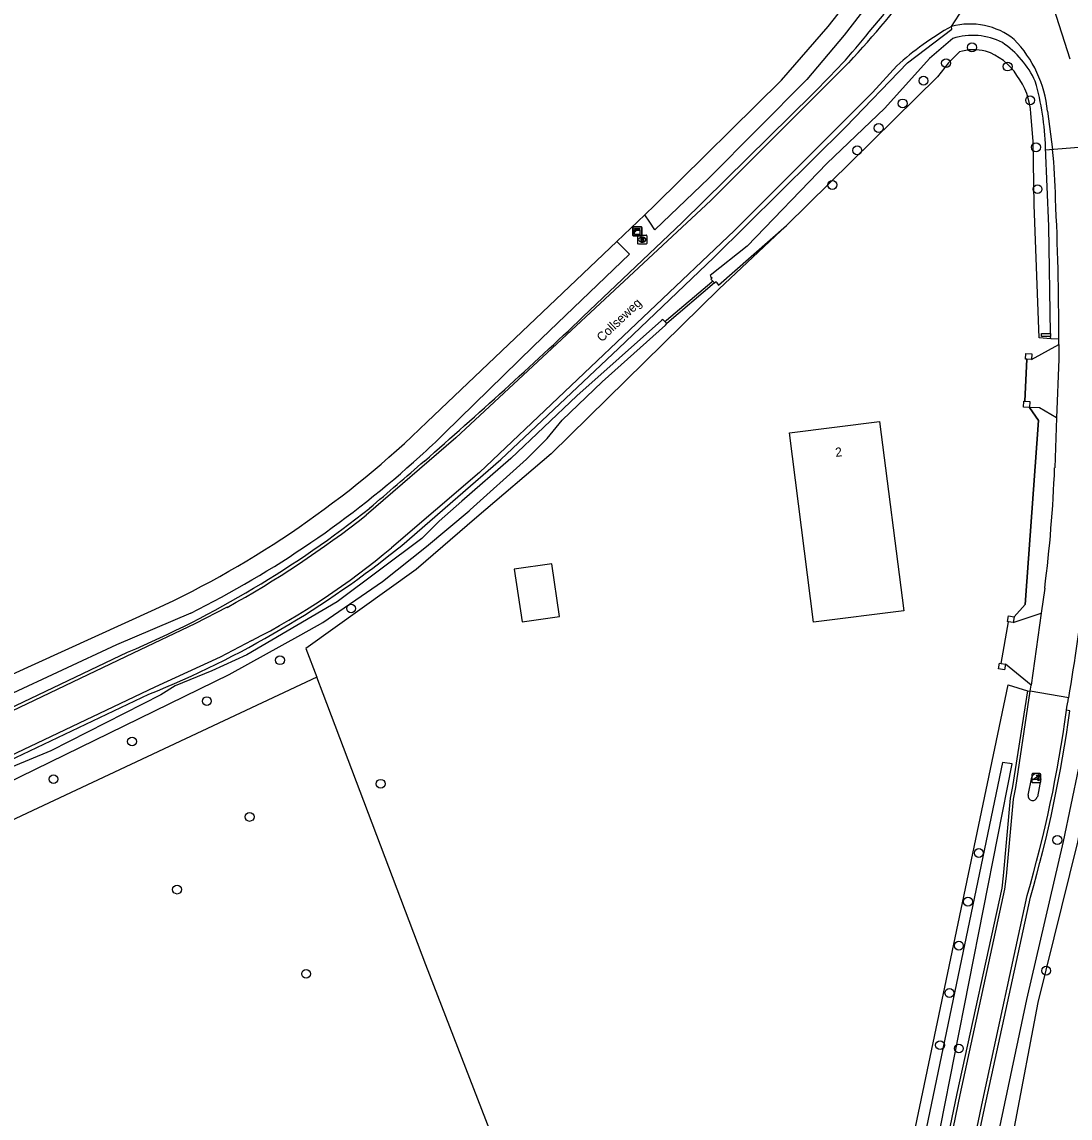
# Model space of a CAD drawing. Extents: x 164494 to 166241, y 382475 to 384494.
# Drawn here: x 165113.4 to 165228.9, y 383751 to 383871.8 of the extents above; entities that cross this region are included whole.
import ezdxf

# ---------------------------------------------------------------- set-up
doc = ezdxf.new("R2010")
doc.units = 0
for name, color, linetype in [('IMGEO_Berm_halfverhard', 7, 'Continuous'), ('IMGEO_Boom', 7, 'Continuous'), ('IMGEO_Bouwland', 7, 'Continuous'), ('IMGEO_Duiker', 7, 'Continuous'), ('IMGEO_Erf', 7, 'Continuous'), ('IMGEO_Groenvoorziening', 7, 'Continuous'), ('IMGEO_Hek', 7, 'Continuous'), ('IMGEO_Kast', 7, 'Continuous'), ('IMGEO_Muur', 7, 'Continuous'), ('IMGEO_Openbare_ruimte_label', 7, 'Continuous'), ('IMGEO_Pand', 7, 'Continuous'), ('IMGEO_Pand_nummerreeks', 7, 'Continuous'), ('IMGEO_Poller', 7, 'Continuous'), ('IMGEO_Rijbaan_lokaal_gesloten', 7, 'Continuous'), ('IMGEO_Rijbaan_lokaal_open', 7, 'Continuous'), ('IMGEO_Rioolput', 7, 'Continuous'), ('IMGEO_Voetpad_open', 7, 'Continuous'), ('IMGEO_Waterloop', 7, 'Continuous')]:
    doc.layers.add(name, color=color, linetype=linetype)

msp = doc.modelspace()

# ---------------------------------------------------------------- linework, layer by layer
at = {"layer": 'IMGEO_Berm_halfverhard'}
for points in [[(165206.74, 383870.72), (165208.37, 383872.67)], [(165155.21, 383814.13), (165161.39, 383819.48), (165166.15, 383823.61), (165179.1, 383835.82), (165189.6, 383845.87), (165204.16, 383860.28), (165210.96, 383867.3), (165215.83, 383871.02), (165215.8, 383871.33)], [(165175.19, 383839.32), (165186.12, 383849.72), (165200.47, 383863.87)], [(165070.12, 383776.3), (165070.84, 383776.64), (165070.9, 383776.54), (165125.01, 383802.35)], [(165072.47, 383771.52), (165073.32, 383771.92), (165073.3, 383772.01), (165127.34, 383797.73)]]:
    msp.add_lwpolyline(points, dxfattribs=at)
for centre, radius, start, end in [((165149.31, 383916.98), 73.74, 313.9288, 321.1451), ((164779.69, 384256.64), 574.96, 311.10726, 313.46198), ((164761.97, 384277.25), 602.13, 310.33243, 311.08901), ((165079.94, 383908.37), 115.2, 293.032, 308.5215), ((165087.22, 383897.79), 107.81, 291.8507, 309.1027)]:
    msp.add_arc(centre, radius, start, end, dxfattribs=at)
at = {"layer": 'IMGEO_Boom'}
for centre in [(165218.05, 383869.02), (165215.2, 383867.28), (165221.98, 383866.91), (165212.71, 383865.35), (165210.42, 383862.84), (165224.46, 383863.19), (165207.77, 383860.13), (165225.11, 383858.01), (165205.41, 383857.67), (165202.67, 383853.86), (165225.28, 383853.39), (165149.64, 383807.17), (165141.8, 383801.47), (165133.74, 383796.96), (165125.5, 383792.51), (165116.84, 383788.36), (165152.89, 383787.85), (165138.45, 383784.2), (165227.46, 383781.65), (165218.81, 383780.22), (165130.46, 383776.19), (165217.61, 383774.86), (165216.61, 383770.01), (165226.23, 383767.25), (165144.68, 383766.9), (165215.57, 383764.79), (165214.54, 383759.04), (165216.61, 383758.67)]:
    msp.add_circle(centre, 0.489, dxfattribs=at)
at = {"layer": 'IMGEO_Bouwland'}
for points in [[(165178.91, 383847.63), (165182.01, 383850.58)], [(165145.85, 383799.61), (165106.62, 383781.19), (165067, 383763.68), (165014.17, 383738.3)], [(165207.26, 383727.36), (165189.95, 383730.66), (165170.64, 383734.86), (165157.89, 383767.91), (165146.55, 383797.78), (165145.85, 383799.61)]]:
    msp.add_lwpolyline(points, dxfattribs=at)
at = {"layer": 'IMGEO_Duiker'}
for points in [[(165226.15, 383857.73), (165232.12, 383858.21)], [(165184.22, 383838.79), (165184.39, 383838.94), (165189.37, 383843.18), (165189.48, 383843.28)]]:
    msp.add_lwpolyline(points, dxfattribs=at)
at = {"layer": 'IMGEO_Erf'}
for points in [[(165224.1, 383834.65), (165223.97, 383834.65), (165224, 383835.29), (165224.64, 383835.26), (165224.61, 383834.62)], [(165224.38, 383829.34), (165223.73, 383829.38), (165223.77, 383830.02), (165223.89, 383830.01)], [(165222.09, 383805.71), (165221.96, 383805.73), (165222.09, 383806.37), (165222.7, 383806.25)], [(165221.74, 383801.03), (165221.63, 383800.4), (165220.99, 383800.51), (165221.1, 383801.14), (165221.26, 383801.11)]]:
    msp.add_lwpolyline(points, dxfattribs=at)
at = {"layer": 'IMGEO_Groenvoorziening'}
for points in [[(165197.6, 383849.39), (165190.2, 383842.41), (165171.67, 383824.21), (165163.5, 383817.22), (165156.8, 383811.47), (165144.65, 383802.77), (165145.85, 383799.61)], [(165189.69, 383843.07), (165184.43, 383838.59)], [(165227.62, 383836.85), (165226.73, 383836.91)], [(165222.7, 383806.25), (165223.9, 383807.6), (165225.39, 383827.88), (165224.38, 383829.34)], [(165222.7, 383806.25), (165222.61, 383805.61)], [(165207.26, 383727.36), (165211.82, 383750), (165222.05, 383798.74), (165224.17, 383798.09)]]:
    msp.add_lwpolyline(points, dxfattribs=at)
at = {"layer": 'IMGEO_Hek'}
for points in [[(165224.1, 383834.65), (165223.89, 383830.01)], [(165224.38, 383829.34), (165225.39, 383827.88), (165223.9, 383807.6), (165222.7, 383806.25)], [(165221.26, 383801.11), (165222.09, 383805.71)]]:
    msp.add_lwpolyline(points, dxfattribs=at)
at = {"layer": 'IMGEO_Kast'}
for p, q in [((165180.67, 383848.32), (165180.67, 383849.16)), ((165180.67, 383849.16), (165180.67, 383848.32)), ((165180.74, 383849.25), (165181.58, 383849.25)), ((165181.58, 383849.25), (165180.74, 383849.25)), ((165181.66, 383849.17), (165181.66, 383848.33)), ((165181.66, 383848.33), (165181.66, 383849.17)), ((165181.59, 383848.25), (165180.75, 383848.25)), ((165180.75, 383848.25), (165181.59, 383848.25))]:
    msp.add_line(p, q, dxfattribs=at)
for points in [[(165180.86, 383849.04), (165181.46, 383849.04), (165181.46, 383848.95), (165180.86, 383848.95), (165180.86, 383849.04)], [(165180.86, 383848.86), (165181.46, 383848.86), (165181.46, 383848.38), (165180.86, 383848.38), (165180.86, 383848.86)]]:
    msp.add_lwpolyline(points, dxfattribs=at)
msp.add_circle((165180.94, 383848.71), 0.0377, dxfattribs=at)
for centre, start, end in [((165180.74, 383849.17), 92.4484, 184.2845), ((165180.74, 383849.17), 92.4484, 184.2845), ((165181.59, 383849.17), 2.4484, 94.2845), ((165181.59, 383849.17), 2.4484, 94.2845), ((165180.74, 383848.33), 182.4484, 274.2845), ((165180.74, 383848.33), 182.4484, 274.2845), ((165181.59, 383848.33), 272.4484, 4.2845), ((165181.59, 383848.33), 272.4484, 4.2845)]:
    msp.add_arc(centre, 0.0779, start, end, dxfattribs=at)
at = {"layer": 'IMGEO_Muur'}
for points in [[(165226.72, 383837.16), (165225.72, 383837.15), (165225.71, 383837.47), (165226.72, 383837.48)], [(165226.72, 383837.48), (165226.72, 383837.16)]]:
    msp.add_lwpolyline(points, dxfattribs=at)
at = {"layer": 'IMGEO_Pand'}
for points in [[(165200.6, 383805.66), (165197.95, 383826.52), (165207.87, 383827.79), (165210.53, 383806.93), (165200.6, 383805.66)], [(165168.47, 383805.69), (165172.6, 383806.29), (165171.75, 383812.09), (165167.62, 383811.49), (165168.47, 383805.69)]]:
    msp.add_lwpolyline(points, dxfattribs=at)
at = {"layer": 'IMGEO_Poller'}
for p, q in [((165224.64, 383788.88), (165224.64, 383788.07)), ((165224.64, 383788.88), (165224.64, 383788.07)), ((165225.54, 383788.98), (165224.74, 383788.98)), ((165225.54, 383788.98), (165224.74, 383788.98)), ((165225.64, 383788.07), (165225.64, 383788.88)), ((165225.64, 383788.07), (165225.64, 383788.88)), ((165224.74, 383787.98), (165225.54, 383787.98)), ((165224.74, 383787.98), (165225.54, 383787.98))]:
    msp.add_line(p, q, dxfattribs=at)
for points in [[(165225.28, 383788.33), (165224.76, 383788.33), (165225.19, 383788.61)], [(165225.32, 383788.71), (165225.31, 383788.63), (165225.18, 383788.84)], [(165225.18, 383788.84), (165225.41, 383788.77), (165225.34, 383788.74)], [(165225.34, 383788.16), (165225.4, 383788.39), (165225.43, 383788.32)], [(165225.47, 383788.3), (165225.54, 383788.29), (165225.34, 383788.16)]]:
    msp.add_lwpolyline(points, dxfattribs=at)
for centre, radius, start, end in [((165224.74, 383788.88), 0.0946, 90, 180), ((165224.74, 383788.88), 0.0946, 90, 180), ((165224.95, 383788.38), 0.332, 351.3247, 42.4854), ((165224.96, 383788.39), 0.476, 351.7527, 41.1691), ((165224.96, 383788.39), 0.516, 349.3569, 42.2912), ((165225.54, 383788.88), 0.0946, 0, 90), ((165225.54, 383788.88), 0.0946, 0, 90), ((165224.74, 383788.07), 0.0946, 180, 270), ((165224.74, 383788.07), 0.0946, 180, 270), ((165225.54, 383788.07), 0.0946, 270, 0), ((165225.54, 383788.07), 0.0946, 270, 0)]:
    msp.add_arc(centre, radius, start, end, dxfattribs=at)
at = {"layer": 'IMGEO_Rijbaan_lokaal_gesloten'}
for points in [[(165215.8, 383871.33), (165217.08, 383873.29)], [(165228.89, 383867.71), (165227.07, 383873.35)], [(165204.49, 383867.34), (165189.28, 383852.13), (165161.16, 383825.98), (165151.31, 383817.47)], [(165209.76, 383866.98), (165207.1, 383864.05), (165191.89, 383848.84), (165163.79, 383822.15), (165154.07, 383813.85)], [(165226.38, 383862), (165226.94, 383857.78)], [(165227.62, 383836.26), (165227.62, 383836.56), (165227.62, 383836.85)], [(165227.62, 383836.26), (165227.61, 383835.46), (165227.61, 383834.66), (165227.37, 383828.18)], [(165227.37, 383828.18), (165227.17, 383822.67)], [(165226.07, 383809.4), (165225.68, 383806.67)], [(165135.98, 383807.3), (165132.42, 383805.48), (165125.61, 383802.24), (165070.35, 383775.84)], [(165225.68, 383806.67), (165224.58, 383798.72)], [(165138.71, 383803.64), (165135.2, 383801.82), (165128.02, 383798.5), (165072.24, 383771.98)], [(165216, 383750), (165216.75, 383753.58), (165221.69, 383776.22), (165221.84, 383777.65), (165222.63, 383786.15), (165222.9, 383787.45), (165224.48, 383798.05)], [(165224.48, 383798.05), (165224.58, 383798.72)], [(165228.71, 383797.33), (165224.48, 383798.05)], [(165224.25, 383786.61), (165224.64, 383788.58)], [(165225.64, 383788.41), (165225.26, 383786.42)], [(165218.62, 383750), (165219.24, 383752.97), (165224.14, 383775.53)]]:
    msp.add_lwpolyline(points, dxfattribs=at)
for centre, radius, start, end in [((165124.54, 383941.84), 109.28, 317.0178, 329.8082), ((165233.31, 383840.69), 35.3, 119.7415, 131.8457), ((165217.84, 383863.8), 7.8, 51.4425, 105.131), ((165213.28, 383860.71), 13.16, 5.5963, 44.2954), ((165160.77, 383851.14), 66.5, 1.0256, 5.7332), ((164929.72, 383837.68), 297.9, 359.8406, 2.8177), ((165075.49, 383828.55), 151.79, 352.7511, 357.7774), ((165026.07, 383832.07), 205.6, 350.2713, 357.2677), ((165081.75, 383905.66), 112.32, 298.8689, 308.266), ((165100.71, 383877.51), 83.07, 297.2226, 309.9697), ((165077.38, 383823.12), 153.5, 349.81, 350.3273), ((165088.76, 383814.86), 140.98, 343.7983, 352.2949), ((165225.14, 383788.47), 0.506, 352.096, 167.7503), ((165224.75, 383786.52), 0.511, 170.4275, 348.2505)]:
    msp.add_arc(centre, radius, start, end, dxfattribs=at)
at = {"layer": 'IMGEO_Rijbaan_lokaal_open'}
for points in [[(165224.17, 383798.09), (165222.51, 383787.54), (165222.26, 383786.26), (165221.48, 383777.69), (165221.33, 383776.35), (165216.37, 383753.71), (165215.6, 383750)], [(165224.17, 383798.09), (165224.48, 383798.05)], [(165228.83, 383795.89), (165228.47, 383795.96)], [(165218.99, 383750), (165219.61, 383752.9), (165224.5, 383775.37)]]:
    msp.add_lwpolyline(points, dxfattribs=at)
msp.add_arc((165084.17, 383815.71), 146.02, 343.9626, 352.2005, dxfattribs=at)
at = {"layer": 'IMGEO_Rioolput'}
for p, q in [((165181.22, 383847.41), (165181.22, 383848.26)), ((165181.29, 383848.33), (165182.15, 383848.33)), ((165181.73, 383847.55), (165181.7, 383847.55)), ((165181.71, 383848.11), (165181.73, 383848.11)), ((165182.22, 383848.26), (165182.22, 383847.41)), ((165182.15, 383847.33), (165181.29, 383847.33))]:
    msp.add_line(p, q, dxfattribs=at)
for points in [[(165181.22, 383847.41), (165181.22, 383848.26)], [(165181.29, 383848.33), (165182.15, 383848.33)], [(165181.81, 383848.03), (165181.55, 383848.03), (165181.55, 383847.63)], [(165181.55, 383847.63), (165181.68, 383847.63), (165181.68, 383847.8), (165181.69, 383847.8)], [(165181.73, 383847.95), (165181.68, 383847.95), (165181.68, 383847.87)], [(165181.68, 383847.87), (165181.73, 383847.87)], [(165181.74, 383847.77), (165181.81, 383847.63), (165181.95, 383847.63), (165181.88, 383847.76)], [(165182.22, 383848.26), (165182.22, 383847.41)], [(165182.15, 383847.33), (165181.29, 383847.33)]]:
    msp.add_lwpolyline(points, dxfattribs=at)
for centre, radius, start, end in [((165181.29, 383848.26), 0.0765, 91.552, 178.448), ((165181.29, 383848.26), 0.0765, 91.552, 178.448), ((165181.69, 383847.74), 0.0533, 26.0293, 88.6989), ((165181.74, 383847.86), 0.0964, 77.0061, 93.1865), ((165181.72, 383848.06), 0.19, 274.7715, 282.9687), ((165181.75, 383847.91), 0.0378, 276.6634, 79.6772), ((165181.81, 383847.92), 0.109, 350.3612, 89.416), ((165181.8, 383847.92), 0.112, 277.5842, 350.9817), ((165181.79, 383847.71), 0.108, 29.5134, 73.7905), ((165182.14, 383848.26), 0.0765, 1.552, 88.448), ((165182.14, 383848.26), 0.0765, 1.552, 88.448), ((165181.29, 383847.41), 0.0765, 181.552, 268.448), ((165181.29, 383847.41), 0.0765, 181.552, 268.448), ((165182.14, 383847.41), 0.0765, 271.552, 358.448), ((165182.14, 383847.41), 0.0765, 271.552, 358.448)]:
    msp.add_arc(centre, radius, start, end, dxfattribs=at)
for centre, major_axis, ratio, start_param, end_param in [((165181.71, 383847.83), (-0.387, 0.002), 0.722429, 4.712389, 7.853982), ((165181.73, 383847.83), (-0.39, 0.002), 0.717154, 1.570796, 4.712389)]:
    msp.add_ellipse(centre, major_axis=major_axis, ratio=ratio, start_param=start_param, end_param=end_param, dxfattribs=at)
at = {"layer": 'IMGEO_Voetpad_open'}
for points in [[(165224.61, 383834.62), (165227.62, 383836.26)], [(165223.89, 383830.01), (165224.1, 383834.65)], [(165224.61, 383834.62), (165224.1, 383834.65)], [(165223.89, 383830.01), (165224.42, 383829.98), (165224.38, 383829.34)], [(165227.37, 383828.18), (165225.5, 383829.28), (165224.38, 383829.34)], [(165222.61, 383805.61), (165225.68, 383806.67)], [(165221.26, 383801.11), (165222.09, 383805.71)], [(165222.61, 383805.61), (165222.09, 383805.71)], [(165221.26, 383801.11), (165221.74, 383801.03)], [(165224.58, 383798.72), (165221.74, 383801.03)]]:
    msp.add_lwpolyline(points, dxfattribs=at)
at = {"layer": 'IMGEO_Waterloop'}
for points in [[(165182.01, 383850.58), (165183.14, 383851.66), (165197.08, 383865.4), (165202.22, 383871.34), (165210.02, 383881.29), (165214.6, 383887.84), (165221.57, 383898.87), (165232.71, 383917.65), (165253.51, 383950.72)], [(165253.51, 383950.72), (165254.42, 383950.13), (165255.25, 383949.6), (165245.53, 383934.16), (165236.56, 383918.92), (165232.41, 383912.89), (165223.55, 383898.77), (165210.14, 383878.39), (165203.98, 383870.35), (165199.84, 383865.48), (165189.04, 383854.61), (165183.1, 383848.91), (165182.55, 383849.75), (165182.01, 383850.58)], [(165215.94, 383869.99), (165213.36, 383867.78), (165208.44, 383862.32), (165202.07, 383856.24), (165193.29, 383847.1), (165189.22, 383843.89), (165189.29, 383843.74), (165189.41, 383843.62), (165189.29, 383843.47), (165189.69, 383843.07)], [(165216.67, 383868.52), (165215.46, 383867.31), (165214.25, 383865.78), (165197.6, 383849.39)], [(165226.73, 383836.91), (165225.47, 383837.01), (165224.91, 383851.66), (165224.8, 383858.7), (165224.54, 383861.72)], [(165226.72, 383837.48), (165226.54, 383849.31), (165226.16, 383857.97)], [(165189.69, 383843.07), (165189.85, 383843.21), (165189.95, 383843.06), (165190.11, 383842.8), (165197.6, 383849.39)], [(165158.01, 383827.73), (165178.91, 383847.63)], [(165178.91, 383847.63), (165179.62, 383846.93), (165180.32, 383846.24), (165169.72, 383836.09), (165159.93, 383826.48)], [(165184.43, 383838.59), (165183.98, 383839.03), (165183.84, 383838.92), (165174.5, 383830.61), (165167.23, 383823.72), (165161.85, 383818.99), (165159.34, 383816.8), (165157.42, 383814.89), (165148.11, 383807.92), (165138.15, 383802.07), (165134.29, 383800.29), (165130.26, 383798.64), (165128.67, 383797.67), (165116.54, 383791.5), (165110.23, 383788.86)], [(165106.54, 383785.41), (165136.21, 383799.88), (165144.08, 383804.26), (165146.53, 383805.62), (165153.11, 383810.16), (165157.96, 383813.99), (165162.65, 383817.94), (165162.75, 383818.03), (165168.95, 383823.63), (165171.25, 383825.9), (165172.9, 383827.92), (165177.29, 383832.16), (165184.29, 383838.42), (165184.43, 383838.59)], [(165226.73, 383836.91), (165226.72, 383837.16)], [(165068.85, 383779.89), (165101.95, 383795.22), (165128.04, 383807.08)], [(165131.96, 383806.67), (165123.79, 383803.17), (165069.86, 383778.04), (165069.54, 383778.63), (165069.4, 383778.89), (165068.85, 383779.89)], [(165232, 383793.29), (165231.32, 383793.72), (165230.62, 383793.62), (165228.12, 383781.47), (165224.06, 383764.09), (165221.07, 383750), (165212.92, 383706.55), (165211.44, 383695.56), (165210.82, 383688.54), (165210.23, 383683.79), (165209.57, 383680.75), (165209.1, 383675.95), (165208.26, 383669.95), (165207.95, 383667.8)], [(165209.32, 383667.69), (165209.55, 383669.75), (165209.51, 383671.77), (165210.36, 383676.67), (165214.71, 383707.74), (165222.75, 383750), (165225.36, 383763.73), (165229.71, 383781.42), (165232, 383793.29)], [(165200.92, 383671.36), (165201.64, 383671.22), (165202.54, 383671.06), (165204.76, 383684.62), (165205.48, 383694), (165206.45, 383702.34), (165210.08, 383727.24), (165214.58, 383750), (165222.49, 383790.05), (165221.4, 383790.2), (165213.05, 383750), (165208.3, 383727.11)]]:
    msp.add_lwpolyline(points, dxfattribs=at)
for centre, radius, start, end in [((165218.15, 383863.29), 7.06, 62.5391, 108.2255), ((165215.48, 383860.85), 10.53, 24.8937, 55.7902), ((165218.26, 383863.2), 5.56, 76.6031, 106.6223), ((165217.51, 383862.39), 6.54, 32.7261, 71.8044), ((165216.84, 383861.3), 7.71, 3.0725, 36.8566), ((165195.46, 383856.96), 30.72, 1.8829, 15.7178), ((165082.64, 383905.02), 107.95, 294.8695, 314.2758), ((165084.52, 383904.02), 108.16, 312.2371, 314.2028), ((165082.34, 383906.36), 111.36, 296.4621, 312.2597)]:
    msp.add_arc(centre, radius, start, end, dxfattribs=at)

# ---------------------------------------------------------------- texts
at = {"layer": 'IMGEO_Openbare_ruimte_label'}
msp.add_text('Collseweg', height=1, rotation=43.6226, dxfattribs=at).set_placement((165177.27, 383836.49))
at = {"layer": 'IMGEO_Pand_nummerreeks'}
msp.add_text('2', height=1, rotation=7.3302, dxfattribs=at).set_placement((165203.05, 383823.87))

doc.saveas('drawing.dxf')
